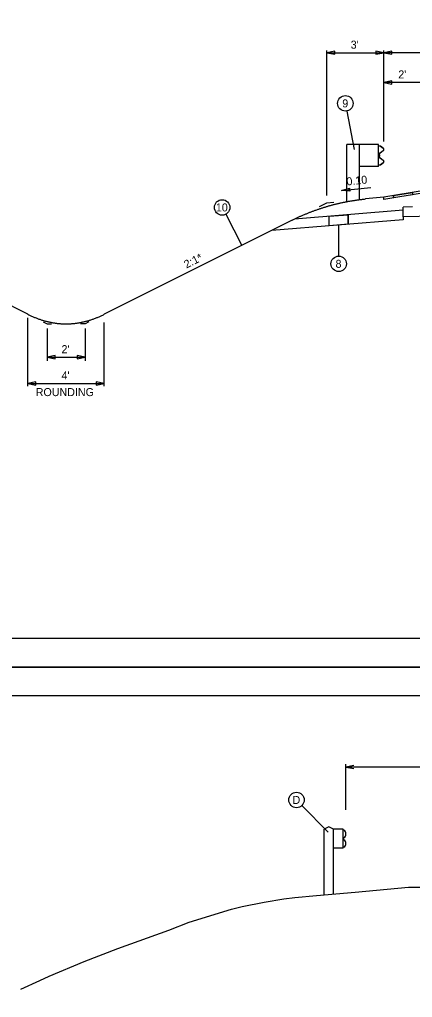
# Model space of a CAD drawing. Extents: x -396 to 156, y -166 to 172.
# Drawn here: x -342.8 to -322.2, y -15.8 to 35.5 of the extents above; entities that cross this region are included whole.
import ezdxf

# ---------------------------------------------------------------- set-up
doc = ezdxf.new("R2010")
doc.units = 0
for name, color, linetype in [('DT_X_Terrain_Ground_Line', 7, 'Continuous'), ('RD_P_Cells', 7, 'Continuous'), ('SH_Border', 7, 'Continuous'), ('SH_Cut_Line', 7, 'Continuous'), ('TX_P_1', 7, 'Continuous'), ('TX_X_1', 7, 'Continuous'), ('XS_P_Finished_Grade', 7, 'Continuous'), ('XS_P_Pavt_Surface', 7, 'Continuous'), ('XS_X_Pavt', 7, 'Continuous')]:
    doc.layers.add(name, color=color, linetype=linetype)

msp = doc.modelspace()

# ---------------------------------------------------------------- linework, layer by layer
at = {"layer": 'DT_X_Terrain_Ground_Line'}
msp.add_lwpolyline([(-342.726, -15.394), (-341.734, -14.93), (-341.238, -14.704), (-339.391, -13.947), (-337.637, -13.252), (-334.955, -12.298), (-333.892, -11.884), (-331.656, -11.192), (-331.098, -11.06), (-329.944, -10.829), (-328.905, -10.663), (-328.342, -10.59), (-327.189, -10.474), (-325.163, -10.299), (-322.357, -10.04), (-321.521, -10.038), (-320.873, -10.059), (-320.686, -10.053), (-319.952, -10.021)], dxfattribs=at)
at = {"layer": 'RD_P_Cells'}
for p, q in [((-324.933, 28.92), (-325.6, 28.92)), ((-325.6, 25.916), (-325.6, 28.92)), ((-323.933, 28.92), (-324.933, 28.92)), ((-324.933, 26.021), (-324.933, 28.92)), ((-323.933, 27.752), (-323.933, 28.92)), ((-323.918, 28.848), (-323.918, 28.848)), ((-323.918, 28.848), (-323.831, 28.832)), ((-323.918, 28.838), (-323.918, 28.848)), ((-323.918, 28.838), (-323.918, 28.838)), ((-323.835, 28.823), (-323.918, 28.838)), ((-323.835, 28.823), (-323.835, 28.823)), ((-323.693, 28.717), (-323.835, 28.823)), ((-323.831, 28.832), (-323.831, 28.832)), ((-323.831, 28.832), (-323.687, 28.725)), ((-323.813, 28.807), (-323.813, 28.807)), ((-323.807, 28.815), (-323.807, 28.815)), ((-323.687, 28.725), (-323.687, 28.725)), ((-323.917, 28.382), (-323.917, 28.382)), ((-323.917, 28.29), (-323.917, 28.382)), ((-323.917, 28.304), (-323.917, 28.367)), ((-323.917, 28.29), (-323.917, 28.29)), ((-323.907, 28.382), (-323.907, 28.382)), ((-323.907, 28.382), (-323.907, 28.29)), ((-323.907, 28.304), (-323.907, 28.367)), ((-323.907, 28.29), (-323.907, 28.29)), ((-323.881, 28.453), (-323.694, 28.591)), ((-323.881, 28.453), (-323.881, 28.453)), ((-323.881, 28.218), (-323.881, 28.218)), ((-323.693, 28.081), (-323.881, 28.218)), ((-323.688, 28.583), (-323.875, 28.445)), ((-323.875, 28.445), (-323.875, 28.445)), ((-323.875, 28.226), (-323.875, 28.226)), ((-323.875, 28.226), (-323.687, 28.089)), ((-323.814, 28.503), (-323.814, 28.503)), ((-323.808, 28.495), (-323.808, 28.495)), ((-323.694, 28.591), (-323.694, 28.591)), ((-323.693, 28.717), (-323.693, 28.717)), ((-323.688, 28.583), (-323.688, 28.583)), ((-323.662, 28.654), (-323.662, 28.654)), ((-323.652, 28.654), (-323.652, 28.654)), ((-323.933, 27.752), (-324.933, 27.752)), ((-323.916, 27.834), (-323.833, 27.849)), ((-323.829, 27.84), (-323.916, 27.824)), ((-323.916, 27.834), (-323.916, 27.834)), ((-323.916, 27.824), (-323.916, 27.834)), ((-323.916, 27.824), (-323.916, 27.824)), ((-323.833, 27.849), (-323.692, 27.955)), ((-323.686, 27.947), (-323.829, 27.84)), ((-323.693, 28.081), (-323.693, 28.081)), ((-323.692, 27.955), (-323.692, 27.955)), ((-323.687, 28.089), (-323.687, 28.089)), ((-323.686, 27.947), (-323.686, 27.947)), ((-323.661, 28.018), (-323.661, 28.018)), ((-323.651, 28.018), (-323.651, 28.018))]:
    msp.add_line(p, q, dxfattribs=at)
for points in [[(-323.899, 28.396), (-323.899, 28.276), (-323.907, 28.276), (-323.907, 28.396)], [(-323.899, 28.364), (-323.899, 28.306), (-323.874, 28.306), (-323.874, 28.364)]]:
    msp.add_lwpolyline(points, close=True, dxfattribs=at)
for centre, radius, start, end in [((-323.741, 28.654), 0.0886, 306.318, 53.2212), ((-323.829, 28.382), 0.0886, 126.318, 180.0944), ((-323.828, 28.29), 0.0886, 180.0944, 233.8707), ((-323.829, 28.382), 0.0788, 126.318, 180.0944), ((-323.828, 28.29), 0.0788, 180.0944, 233.8707), ((-323.741, 28.654), 0.0787, 306.318, 53.2212), ((-323.739, 28.018), 0.0787, 306.9675, 53.8707), ((-323.739, 28.018), 0.0886, 306.9675, 53.8707)]:
    msp.add_arc(centre, radius, start, end, dxfattribs=at)
at = {"layer": 'SH_Border'}
for points in [[(-354.402, 66.004), (-258.402, 66.004), (-258.402, 3.004), (-354.402, 3.004)], [(-354.402, 0.004), (-258.402, 0.004), (-258.402, -62.996), (-354.402, -62.996)]]:
    msp.add_lwpolyline(points, close=True, dxfattribs=at)
at = {"layer": 'SH_Cut_Line'}
for points in [[(-358.902, 1.504), (-256.902, 1.504), (-256.902, 67.504), (-358.902, 67.504)], [(-358.902, -64.496), (-256.902, -64.496), (-256.902, 1.504), (-358.902, 1.504)]]:
    msp.add_lwpolyline(points, close=True, dxfattribs=at)
at = {"layer": 'TX_P_1'}
for p, q in [((-326.652, 26.239), (-326.652, 33.843)), ((-326.652, 33.728), (-323.652, 33.728)), ((-326.232, 33.644), (-326.232, 33.812)), ((-324.072, 33.812), (-324.072, 33.644)), ((-323.652, 29.065), (-323.652, 33.843)), ((-308.652, 33.728), (-323.652, 33.728)), ((-323.232, 33.644), (-323.232, 33.812)), ((-321.652, 32.169), (-323.652, 32.169)), ((-323.232, 32.085), (-323.232, 32.253)), ((-325.878, 26.502), (-324.343, 26.656)), ((-325.468, 26.627), (-325.452, 26.46)), ((-322.652, 25.46), (-328.348, 25.004)), ((-322.652, 24.959), (-329.545, 24.407)), ((-322.652, 25.125), (-322.652, 24.959)), ((-342.35, 16.241), (-342.35, 19.826)), ((-338.35, 16.241), (-338.35, 19.581)), ((-341.35, 19.267), (-341.35, 17.566)), ((-339.35, 19.267), (-339.35, 17.566)), ((-341.35, 17.756), (-339.35, 17.756)), ((-340.93, 17.672), (-340.93, 17.84)), ((-339.77, 17.84), (-339.77, 17.672)), ((-341.93, 16.296), (-341.93, 16.464)), ((-338.77, 16.464), (-338.77, 16.296)), ((-342.35, 16.38), (-338.35, 16.38))]:
    msp.add_line(p, q, dxfattribs=at)
for points in [[(-326.232, 33.812), (-326.652, 33.728), (-326.232, 33.644)], [(-324.072, 33.644), (-323.652, 33.728), (-324.072, 33.812)], [(-323.232, 33.812), (-323.652, 33.728), (-323.232, 33.644)], [(-323.232, 32.253), (-323.652, 32.169), (-323.232, 32.085)], [(-325.452, 26.46), (-325.878, 26.502), (-325.468, 26.627)], [(-327.042, 25.659), (-326.652, 25.854), (-326.277, 25.891)], [(-341.553, 19.606), (-341.35, 19.504), (-341.108, 19.504)], [(-339.148, 19.606), (-339.35, 19.504), (-339.593, 19.504)], [(-340.93, 17.84), (-341.35, 17.756), (-340.93, 17.672)], [(-339.77, 17.672), (-339.35, 17.756), (-339.77, 17.84)], [(-341.93, 16.464), (-342.35, 16.38), (-341.93, 16.296)], [(-338.77, 16.296), (-338.35, 16.38), (-338.77, 16.464)]]:
    msp.add_lwpolyline(points, dxfattribs=at)
for points in [[(-323.158, 26.109), (-323.158, 26.234), (-322.158, 26.396), (-322.158, 26.271)], [(-325.53, 25.23), (-325.53, 24.728), (-326.53, 24.648), (-326.53, 25.15)]]:
    msp.add_lwpolyline(points, close=True, dxfattribs=at)
for centre in [(-325.68, 31.068), (-332.153, 25.611), (-326.03, 22.653), (-328.246, -5.467)]:
    msp.add_circle(centre, 0.406, dxfattribs=at)
at = {"layer": 'TX_X_1'}
for p, q in [((-325.602, 30.669), (-325.209, 28.646)), ((-323.158, 26.234), (-323.158, 26.109)), ((-331.965, 25.251), (-331.113, 23.623)), ((-326.53, 24.648), (-326.53, 25.15)), ((-325.53, 24.728), (-325.53, 25.23)), ((-326.03, 23.059), (-326.03, 24.688)), ((-325.652, -5.988), (-325.652, -3.59)), ((-308.652, -3.743), (-325.652, -3.743)), ((-327.961, -5.757), (-326.585, -7.155))]:
    msp.add_line(p, q, dxfattribs=at)
msp.add_lwpolyline([(-325.232, -3.659), (-325.652, -3.743), (-325.232, -3.827)], dxfattribs=at)
at = {"layer": 'XS_P_Finished_Grade'}
for p, q in [((-323.652, 26.154), (-324.628, 26.056)), ((-328.471, 24.944), (-338.35, 20.004)), ((-342.35, 20.004), (-344.594, 21.126))]:
    msp.add_line(p, q, dxfattribs=at)
for points in [[(-328.471, 24.944), (-328.401, 24.979), (-328.331, 25.013), (-328.26, 25.047), (-328.19, 25.08), (-328.119, 25.113), (-328.048, 25.145), (-327.977, 25.176), (-327.906, 25.207), (-327.835, 25.238), (-327.764, 25.268), (-327.692, 25.297), (-327.62, 25.326), (-327.549, 25.355), (-327.477, 25.383), (-327.404, 25.41), (-327.332, 25.437), (-327.26, 25.463), (-327.187, 25.489), (-327.114, 25.514), (-327.041, 25.539), (-326.968, 25.563), (-326.895, 25.587), (-326.822, 25.61), (-326.748, 25.633), (-326.675, 25.655), (-326.601, 25.677), (-326.527, 25.698), (-326.453, 25.719), (-326.378, 25.739), (-326.304, 25.758), (-326.229, 25.777), (-326.155, 25.796), (-326.08, 25.814), (-326.005, 25.831), (-325.93, 25.848), (-325.854, 25.864), (-325.779, 25.88), (-325.703, 25.896), (-325.627, 25.911), (-325.551, 25.925), (-325.475, 25.939), (-325.399, 25.952), (-325.323, 25.965), (-325.246, 25.977), (-325.17, 25.989), (-325.093, 26), (-325.016, 26.011), (-324.939, 26.021), (-324.861, 26.03), (-324.784, 26.039), (-324.706, 26.048), (-324.628, 26.056)], [(-342.35, 20.004), (-342.273, 19.967), (-342.197, 19.93), (-342.12, 19.896), (-342.043, 19.862), (-341.966, 19.831), (-341.889, 19.8), (-341.812, 19.771), (-341.735, 19.744), (-341.658, 19.718), (-341.581, 19.694), (-341.504, 19.671), (-341.427, 19.649), (-341.35, 19.629), (-341.273, 19.611), (-341.197, 19.594), (-341.12, 19.578), (-341.043, 19.564), (-340.966, 19.552), (-340.889, 19.541), (-340.812, 19.531), (-340.735, 19.523), (-340.658, 19.516), (-340.581, 19.511), (-340.504, 19.507), (-340.427, 19.505), (-340.35, 19.504), (-340.273, 19.505), (-340.197, 19.507), (-340.12, 19.511), (-340.043, 19.516), (-339.966, 19.523), (-339.889, 19.531), (-339.812, 19.541), (-339.735, 19.552), (-339.658, 19.564), (-339.581, 19.578), (-339.504, 19.594), (-339.427, 19.611), (-339.35, 19.629), (-339.273, 19.649), (-339.197, 19.671), (-339.12, 19.694), (-339.043, 19.718), (-338.966, 19.744), (-338.889, 19.771), (-338.812, 19.8), (-338.735, 19.831), (-338.658, 19.862), (-338.581, 19.896), (-338.504, 19.93), (-338.427, 19.967), (-338.35, 20.004)]]:
    msp.add_spline(points, degree=3, dxfattribs=at)
at = {"layer": 'XS_P_Pavt_Surface'}
for p, q in [((-321.652, 26.479), (-323.652, 26.154)), ((-321.652, 26.354), (-323.652, 26.029)), ((-323.652, 26.029), (-323.652, 26.154)), ((-322.152, 25.635), (-322.652, 25.625)), ((-322.652, 25.125), (-322.652, 25.625)), ((-319.652, 25.185), (-322.652, 25.125))]:
    msp.add_line(p, q, dxfattribs=at)
at = {"layer": 'XS_X_Pavt'}
for p, q in [((-326.552, -6.878), (-326.802, -7.003)), ((-326.802, -10.441), (-326.802, -7.003)), ((-326.302, -7.003), (-326.552, -6.878)), ((-325.802, -7.003), (-326.302, -7.003)), ((-326.302, -10.397), (-326.302, -7.003)), ((-325.802, -8.003), (-325.802, -7.003)), ((-325.752, -7.053), (-325.802, -7.053)), ((-325.802, -8.003), (-326.302, -8.003)), ((-325.752, -7.953), (-325.802, -7.953))]:
    msp.add_line(p, q, dxfattribs=at)
for centre, radius, start, end in [((-325.902, -7.253), 0.25, 306.8699, 53.1301), ((-325.752, -7.503), 0.05, 90, 270), ((-325.902, -7.753), 0.25, 306.8699, 53.1301)]:
    msp.add_arc(centre, radius, start, end, dxfattribs=at)

# ---------------------------------------------------------------- texts
at = {"layer": 'TX_P_1'}
for s, p in [("3'", (-325.4, 33.938)), ("2'", (-322.9, 32.379)), ('9', (-325.841, 30.858)), ('10', (-332.482, 25.401)), ('8', (-326.196, 22.443)), ("2'", (-340.589, 17.966)), ("4'", (-340.589, 16.59)), ('ROUNDING', (-341.944, 15.715)), ('D', (-328.455, -5.677))]:
    msp.add_text(s, height=0.42, dxfattribs=at).set_placement(p)
msp.add_text('2:1*', height=0.42, rotation=26.5651, dxfattribs=at).set_placement((-334.028, 22.4))
at = {"layer": 'XS_P_Finished_Grade'}
msp.add_text('0.10', height=0.42, rotation=5.7106, dxfattribs=at).set_placement((-325.602, 26.76))

doc.saveas('drawing.dxf')
